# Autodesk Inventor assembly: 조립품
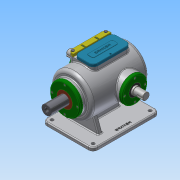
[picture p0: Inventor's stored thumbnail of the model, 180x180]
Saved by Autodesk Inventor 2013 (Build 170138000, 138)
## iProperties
Created: 2018-08
Part Number: 조립품
Document SubType Name: Assembly
Designer: Administrator
Author: Administrator
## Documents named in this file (15)
- C:\Users\Administrator\Desktop\380808V1009\공용부품_20180825_1\조립품.iam
- C:\Users\Administrator\Desktop\380808V1009\공용부품_20180825_1\본체.ipt
- C:\Users\Administrator\Desktop\380808V1009\공용부품_20180825_1\축 커버.ipt
- C:\Users\Administrator\Desktop\380808V1009\공용부품_20180825_1\베어링 6205.ipt
- 베어링 6205.ipt
- C:\Users\Administrator\Desktop\380808V1009\공용부품_20180825_1\오일 실 25 38 8.ipt
- C:\Users\Administrator\Desktop\380808V1009\공용부품_20180825_1\볼트 M4x0.7.ipt
- C:\Users\Administrator\Desktop\380808V1009\공용부품_20180825_1\편심축.ipt
- C:\Users\Administrator\Desktop\380808V1009\공용부품_20180825_1\상부커버.ipt
- C:\Users\Administrator\Desktop\380808V1009\공용부품_20180825_1\고정플레이트.ipt
- C:\Users\Administrator\Desktop\380808V1009\공용부품_20180825_1\육각머리볼트 M4.ipt
- C:\Users\Administrator\Desktop\380808V1009\공용부품_20180825_1\슬라이드.ipt
- C:\Users\Administrator\Desktop\380808V1009\공용부품_20180825_1\부시.ipt
- C:\Users\Administrator\Desktop\380808V1009\공용부품_20180825_1\슬라이드 커버.ipt
- C:\Users\Administrator\Desktop\380808V1009\공용부품_20180825_1\가변스프링.ipt
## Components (14 placed, 3 different names)
1. 고정플레이트:1
2. 가변스프링:1
3. M4x0.7:1
4. M4x0.7:2
5. M4x0.7:3
6. M4x0.7:4
7. M4x0.7:5
8. M4x0.7:6
9. M4x0.7:7
10. M4x0.7:8
11. M4x0.7:9
12. M4x0.7:10
13. M4x0.7:11
14. M4x0.7:12
